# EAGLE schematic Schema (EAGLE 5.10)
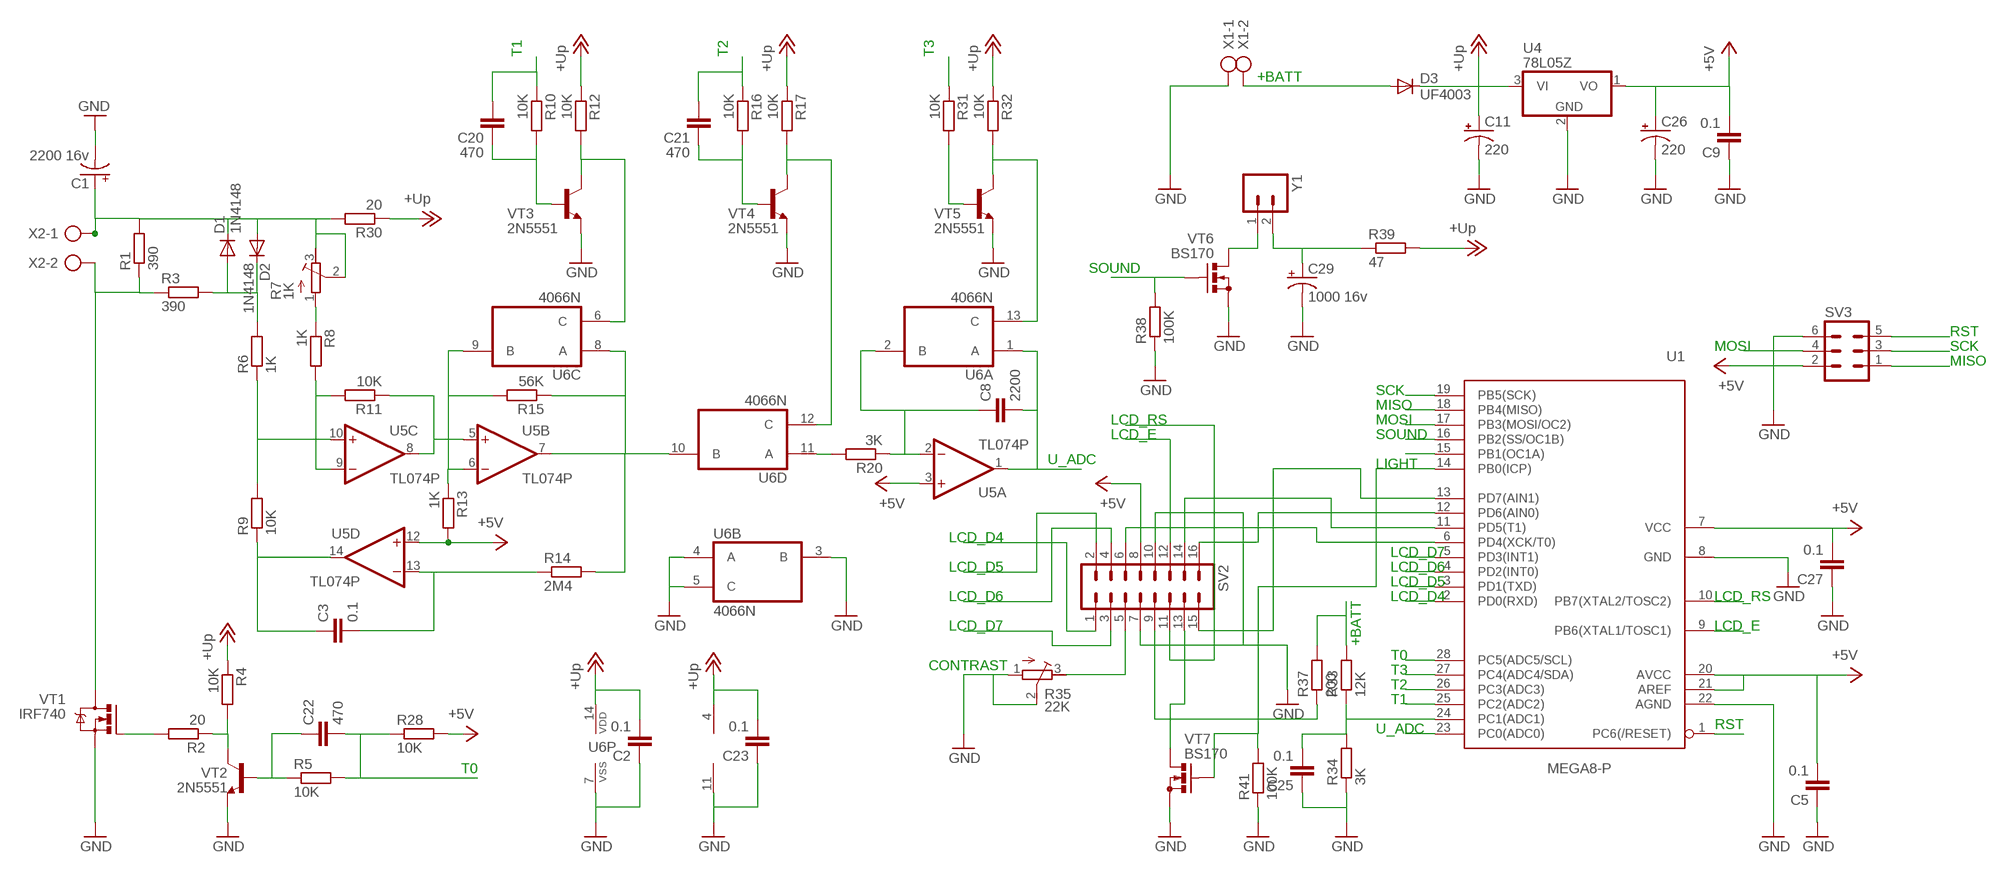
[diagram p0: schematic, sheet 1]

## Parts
C1  2200 16v  CPOL-USE5-10.5  [E5-10,5]
C2  0.1  C-EU050-035X075  [C050-035X075]
C3  0.1  C-EU050-035X075  [C050-035X075]
C5  0.1  C-EU050-035X075  [C050-035X075]
C8  2200  C-EU050-035X075  [C050-035X075]
C9  0.1  C-EU050-035X075  [C050-035X075]
C11  220  CPOL-USE2.5-7  [E2,5-7]
C20  470  C-EU075-032X103  [C075-032X103]
C21  470  C-EU075-032X103  [C075-032X103]
C22  470  C-EU050-035X075  [C050-035X075]
C23  0.1  C-EU050-035X075  [C050-035X075]
C25  0.1  C-EU050-035X075  [C050-035X075]
C26  220  CPOL-USE2.5-7  [E2,5-7]
C27  0.1  C-EU050-035X075  [C050-035X075]
C29  1000 16v  CPOL-USE5-10.5  [E5-10,5]
D1  1N4148  DIODE-D-7.5  [D-7.5]
D2  1N4148  DIODE-D-7.5  [D-7.5]
D3  UF4003  [DO41-10]
R1  390  R-EU_0309/12  [0309/12]
R2  20  R-EU_0207/10  [0207/10]
R3  390  R-EU_0309/12  [0309/12]
R4  10K  R-EU_0207/10  [0207/10]
R5  10K  R-EU_0207/10  [0207/10]
R6  1K  R-EU_0207/10  [0207/10]
R7  1K  R-TRIMM3296Y  [RTRIM3296Y]
R8  1K  R-EU_0207/10  [0207/10]
R9  10K  R-EU_0207/10  [0207/10]
R10  10K  R-EU_0207/10  [0207/10]
R11  10K  R-EU_0207/10  [0207/10]
R12  10K  R-EU_0207/10  [0207/10]
R13  1K  R-EU_0207/10  [0207/10]
R14  2M4  R-EU_0207/12  [0207/12]
R15  56K  R-EU_0207/10  [0207/10]
R16  10K  R-EU_0207/10  [0207/10]
R17  10K  R-EU_0207/10  [0207/10]
R20  3K  R-EU_0207/10  [0207/10]
R28  10K  R-EU_0207/10  [0207/10]
R30  20  R-EU_0207/10  [0207/10]
R31  10K  R-EU_0207/10  [0207/10]
R32  10K  R-EU_0207/10  [0207/10]
R33  12K  R-EU_0207/10  [0207/10]
R34  3K  R-EU_0207/10  [0207/10]
R35  22K  R-TRIMM64W  [RTRIM64W]
R37  200  R-EU_0309/12  [0309/12]
R38  100K  R-EU_0207/10  [0207/10]
R39  47  R-EU_0207/10  [0207/10]
R41  100K  R-EU_0207/10  [0207/10]
SV2  ML16  [ML16]
SV3  ML6  [ML6]
U1  MEGA8-P  [DIL28-3]
U4  78L05Z  [TO92]
U5  TL074P  [DIL14]
U6  4066N  [DIL14]
VT1  IRF740  [TO220BV]
VT2  2N5551  2N5551-NPN-TO92-CBE  [TO92-CBE]
VT3  2N5551  2N5551-NPN-TO92-CBE  [TO92-CBE]
VT4  2N5551  2N5551-NPN-TO92-CBE  [TO92-CBE]
VT5  2N5551  2N5551-NPN-TO92-CBE  [TO92-CBE]
VT6  BS170  [SOT54E]
VT7  BS170  [SOT54E]
X1  AK500/2  [AK500/2]
X2  AK500/2  [AK500/2]
Y1  M02  [02P]

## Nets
+5V: C5.2 C9.2 C26.+ C27.2 R13.2 R28.2 SV2.8 SV3.2 U1.7(VCC) U1.20(AVCC) U1.21(AREF) U4.1(VO) U5.3(A:+IN) U5.12(D:+IN)
+12V: C2.2 C11.+ C23.2 D3.C R4.1 R12.1 R17.1 R30.1 R32.1 R39.2 U4.3(VI) U5.4(P:V+) U6.14(P:VDD) ; supply symbol labelled +Up
+BATT: D3.A R33.2 R37.2 X1.2
GND: C1.- C2.1 C5.1 C9.1 C11.- C23.1 C25.1 C26.- C27.1 C29.- R34.1 R35.1(E) R35.2(S) R38.1 R41.1 SV2.7 SV2.10 U1.8(GND) U1.22(AGND) U4.2(GND) U5.11(P:V-) U6.3(B:B) U6.4(B:A) U6.5(B:C) U6.7(P:VSS) VT1.S VT2.E VT3.E VT4.E VT5.E VT6.S VT7.S X1.1
LCD_D4: SV2.1 U1.2(PD0(RXD))
LCD_D5: SV2.2 U1.3(PD1(TXD))
LCD_D6: SV2.4 U1.4(PD2(INT0))
LCD_D7: SV2.3 U1.5(PD3(INT1))
LCD_E: SV2.12 U1.9(PB6(XTAL1/TOSC1))
LCD_RS: SV2.11 U1.10(PB7(XTAL2/TOSC2))
LIGHT: R41.2 U1.14(PB0(ICP)) VT7.G
MISO: SV3.1 U1.18(PB4(MISO))
MOSI: SV3.4 U1.17(PB3(MOSI/OC2))
N$1: C1.+ D1.C D2.A R1.2 R7.2(S) R7.3(A) R30.2 X2.1
N$2: R1.1 R3.1 VT1.D X2.2
N$3: D1.A D2.C R3.2 R6.2
N$4: R13.1 R15.2 U5.6(B:-IN) U6.9(C:B)
N$5: R7.1(E) R8.1
N$6: R6.1 R9.2 U5.10(C:+IN)
N$7: C3.1 R9.1 U5.14(D:OUT)
N$8: R8.2 R11.2 U5.9(C:-IN)
N$9: R11.1 U5.5(B:+IN) U5.8(C:OUT)
N$10: R14.2 R15.1 U5.7(B:OUT) U6.8(C:A) U6.10(D:B)
N$11: R12.2 U6.6(C:C) VT3.C
N$12: C3.2 R14.1 U5.13(D:-IN)
N$13: C20.1 R10.2 VT3.B
N$14: R37.1 SV2.9
N$15: R17.2 U6.12(D:C) VT4.C
N$16: C21.1 R16.2 VT4.B
N$17: R32.2 U6.13(A:C) VT5.C
N$18: VT6.D Y1.1
N$19: R31.2 VT5.B
N$20: C29.+ R39.1 Y1.2
N$21: R20.2 U6.11(D:A)
N$22: C8.1 R20.1 U5.2(A:-IN) U6.2(A:B)
N$23: SV3.6
N$24: C22.1 R5.1 VT2.B
N$25: C25.2 R33.1 R34.2 U1.24(PC1(ADC1))
N$26: R2.1 R4.2 VT2.C
N$27: R2.2 VT1.G
N$28: SV2.13 VT7.D
N$40: U1.15(PB1(OC1A))
N$42: SV2.15 U1.13(PD7(AIN1))
N$43: SV2.16 U1.12(PD6(AIN0))
N$44: SV2.14 U1.11(PD5(T1))
N$45: SV2.6 U1.6(PD4(XCK/T0))
N$55: R35.3(A) SV2.5
RST: SV3.5 U1.1(PC6(/RESET))
SCK: SV3.3 U1.19(PB5(SCK))
SOUND: R38.2 U1.16(PB2(SS/OC1B)) VT6.G
T0: C22.2 R5.2 R28.1 U1.28(PC5(ADC5/SCL))
T1: C20.2 R10.1 U1.25(PC2(ADC2))
T2: C21.2 R16.1 U1.26(PC3(ADC3))
T3: R31.1 U1.27(PC4(ADC4/SDA))
U_ADC: C8.2 U1.23(PC0(ADC0)) U5.1(A:OUT) U6.1(A:A)

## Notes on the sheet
- T1 | T2 | T3
- +BATT
- SOUND
- RST
- MOSI | SCK
- MISO
- SCK
- MISO
- LCD_RS | MOSI
- LCD_E | SOUND
- U_ADC
- LIGHT
- LCD_D4
- LCD_D7
- LCD_D5 | LCD_D6
- LCD_D5
- LCD_D6 | LCD_D4 | LCD_RS
- LCD_D7 | LCD_E
- +BATT
- CONTRAST | T0
- T3
- T2
- T1
- RST
- U_ADC
- T0

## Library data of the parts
C1 C11 C26 C29 = rcl:CPOL-US: POLARIZED CAPACITOR, American symbol
C2 C3 C5 C8 C9 C20-C23 C25 C27 = rcl:C-EU: CAPACITOR, European symbol
D1 D2 = diode:DIODE-: DIODE
D3 = diode:UF4003: DIODE
R1-R6 R8-R17 R20 R28 R30-R34 R37-R39 R41 = rcl:R-EU_: RESISTOR, European symbol
R7 R35 = rcl:R-TRIMM: Trimm resistor
SV2 = con-harting-ml:ML16: HARTING
SV3 = con-harting-ml:ML6: HARTING
U1 = atmel:MEGA8-P: MICROCONTROLLER 8 Kbytes FLASH 1 kbytes SRAM 512 bytes EEPROM USART 4-channel 10 bit ADC 2-channel 8 bit ADC Source: avr.lbr
U4 = linear:78*: Positive VOLTAGE REGULATOR Source: http://cache.national.com/ds/LM/LM78L05.pdf http://www.fairchildsemi.com/ds/LM/LM7805.pdf
U5 = linear:TL074: OP AMP
U6 = 40xx:4066: Quad bilateral ANALOG SWITCH
VT1 = transistor-power:IRF740: N-CHANNEL MOS FET
VT2-VT5 = transistor:*-NPN-: NPN Transistror
VT6 VT7 = transistor-small-signal:BS170: N-CHANNEL MOS FET
X1 X2 = con-ptr500:AK500/2: CONNECTOR
Y1 = con-amp-quick:M02: AMP QUICK CONNECTOR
